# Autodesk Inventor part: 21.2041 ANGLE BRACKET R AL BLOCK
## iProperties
Created: 2007-01
Part Number: 21.2041 ANGLE BRACKET R AL BLOCK
Document SubType Name: Modeling
Designer: Andy Moles
Material: Aluminum-6061
Density: 2.71 g/cm^3
Mass: 103.451 g
Surface Area: 106.978 cm^2
Volume: 38.1736 cm^3
Author: Andy Moles
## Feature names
1. Extrusion1
2. Extrusion5
3. Extrusion2
4. Extrusion4
5. Extrusion6
6. Extrusion7
7. Circular Pattern1
8. Extrusion8
9. Fillet2
